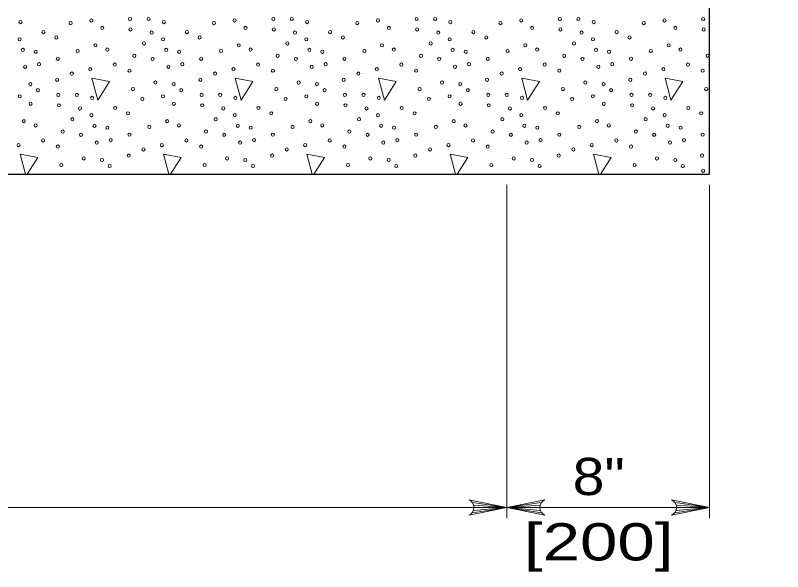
# Model space of a CAD drawing. Extents: x 1352.5 to 1386.5, y 735.9 to 779.9.
# Drawn here: x 1364.306 to 1367.523, y 768.997 to 771.328 of the extents above; entities that cross this region are included whole.
import ezdxf
from ezdxf.enums import TextEntityAlignment as Align

# ---------------------------------------------------------------- set-up
doc = ezdxf.new("R2010")
doc.units = 0
doc.header["$LTSCALE"] = 0.062
doc.layers.add('1', color=7, linetype='Continuous', lineweight=13)

msp = doc.modelspace()

# ---------------------------------------------------------------- linework, layer by layer
at = {"layer": '1'}
for p, q in [((1364.32675, 770.747), (1364.34892, 770.6625)), ((1364.4005, 770.73258), (1364.32675, 770.747)), ((1364.35592, 770.6625), (1364.4005, 770.73258)), ((1364.9275, 770.747), (1364.94967, 770.6625)), ((1365.00125, 770.73258), (1364.9275, 770.747)), ((1364.95667, 770.6625), (1365.00125, 770.73258)), ((1365.52825, 770.747), (1365.5505, 770.6625)), ((1365.602, 770.73258), (1365.52825, 770.747)), ((1365.55733, 770.6625), (1365.602, 770.73258)), ((1366.129, 770.747), (1366.15117, 770.66242)), ((1366.20275, 770.73258), (1366.129, 770.747)), ((1366.15808, 770.66242), (1366.20275, 770.73258)), ((1366.72975, 770.747), (1366.752, 770.66242)), ((1366.8035, 770.73258), (1366.72975, 770.747)), ((1366.75883, 770.66242), (1366.8035, 770.73258)), ((1366.36658, 770.61742), (1366.36658, 769.22067)), ((1367.21625, 770.61742), (1367.21625, 769.22067)), ((1366.22242, 769.28583), (1366.36658, 769.26567)), ((1366.51083, 769.28583), (1366.36658, 769.26567)), ((1367.072, 769.28583), (1367.21625, 769.26567)), ((1366.22067, 769.24333), (1366.36658, 769.26567)), ((1366.22625, 769.25275), (1366.36658, 769.26567)), ((1366.22725, 769.27583), (1366.36658, 769.26567)), ((1366.22875, 769.26567), (1366.36658, 769.26567)), ((1366.50592, 769.27583), (1366.36658, 769.26567)), ((1366.5045, 769.26567), (1366.36658, 769.26567)), ((1366.507, 769.25275), (1366.36658, 769.26567)), ((1366.5125, 769.24333), (1366.36658, 769.26567)), ((1367.07033, 769.24333), (1367.21625, 769.26567)), ((1367.07583, 769.25275), (1367.21625, 769.26567)), ((1367.07692, 769.27583), (1367.21625, 769.26567)), ((1367.07833, 769.26567), (1367.21625, 769.26567))]:
    msp.add_line(p, q, dxfattribs=at)
at = {"layer": '1', "lineweight": 25}
msp.add_lwpolyline([(1358.38042, 774.73258), (1359.56983, 774.73258), (1359.56983, 770.66242), (1367.21625, 770.66242), (1367.21625, 774.73258), (1368.40567, 774.73258), (1369.78625, 774.73258)], dxfattribs=at)
at = {"layer": '1'}
for points in [[(1364.62717, 771.065), (1364.65142, 770.97283), (1364.70083, 771.05067)], [(1365.22783, 771.065), (1365.25217, 770.97283), (1365.30167, 771.05067)], [(1365.82858, 771.065), (1365.85292, 770.97283), (1365.90242, 771.05067)], [(1366.42942, 771.065), (1366.45367, 770.97283), (1366.50308, 771.05067)], [(1367.03017, 771.065), (1367.05442, 770.97283), (1367.10392, 771.05067)]]:
    msp.add_lwpolyline(points, close=True, dxfattribs=at)
for points in [[(1366.20733, 769.23383), (1366.36658, 769.26567), (1366.20733, 769.2975)], [(1366.52592, 769.23383), (1366.36658, 769.26567), (1366.52592, 769.2975)], [(1367.05692, 769.23383), (1367.21625, 769.26567), (1367.05692, 769.2975)], [(1359.56983, 769.26567), (1360.1195, 769.26567), (1360.41942, 769.26567), (1363.67817, 769.26567), (1366.36658, 769.26567), (1366.95142, 769.26567), (1367.21625, 769.26567)]]:
    msp.add_lwpolyline(points, dxfattribs=at)
for centre, start, end in [((1366.19445, 769.2657), 292.08605, 67.91218), ((1366.53878, 769.2657), 112.08782, 247.91395), ((1367.04405, 769.2657), 292.08605, 67.91218)]:
    msp.add_arc(centre, 0.03438, start, end, dxfattribs=at)
for centre in [(1364.62447, 771.30712), (1364.78642, 771.3131), (1364.86432, 771.3131), (1365.22523, 771.30712), (1365.38718, 771.3131), (1365.46508, 771.3131), (1365.82599, 771.30712), (1365.98794, 771.3131), (1366.06584, 771.3131), (1366.42674, 771.30712), (1366.5887, 771.3131), (1366.6666, 771.3131), (1367.0275, 771.30712), (1367.18946, 771.3131), (1364.32759, 771.30023), (1364.53771, 771.29593), (1364.67018, 771.2759), (1364.92835, 771.30023), (1365.13847, 771.29593), (1365.27094, 771.2759), (1365.52911, 771.30023), (1365.73923, 771.29593), (1365.87169, 771.2759), (1366.12987, 771.30023), (1366.33998, 771.29593), (1366.47245, 771.2759), (1366.73063, 771.30023), (1366.94074, 771.29593), (1367.07321, 771.2759), (1364.42412, 771.25814), (1364.78883, 771.26932), (1364.87729, 771.25645), (1365.02487, 771.25814), (1365.38958, 771.26932), (1365.47805, 771.25645), (1365.62563, 771.25814), (1365.99034, 771.26932), (1366.0788, 771.25645), (1366.22639, 771.25814), (1366.5911, 771.26932), (1366.67956, 771.25645), (1366.82715, 771.25814), (1367.19186, 771.26932), (1364.32434, 771.22809), (1364.47763, 771.23583), (1364.8456, 771.21092), (1364.9251, 771.22809), (1365.07839, 771.23583), (1365.44636, 771.21092), (1365.52586, 771.22809), (1365.67915, 771.23583), (1366.04711, 771.21092), (1366.12661, 771.22809), (1366.27991, 771.23583), (1366.64787, 771.21092), (1366.72737, 771.22809), (1366.88067, 771.23583), (1364.33736, 771.18346), (1364.39168, 771.17567), (1364.56715, 771.1789), (1364.64179, 771.20291), (1364.69125, 771.18489), (1364.93812, 771.18346), (1364.99243, 771.17567), (1365.16791, 771.1789), (1365.24255, 771.20291), (1365.29201, 771.18489), (1365.53887, 771.18346), (1365.59319, 771.17567), (1365.76866, 771.1789), (1365.84331, 771.20291), (1365.89277, 771.18489), (1366.13963, 771.18346), (1366.19395, 771.17567), (1366.36942, 771.1789), (1366.44407, 771.20291), (1366.49353, 771.18489), (1366.74039, 771.18346), (1366.79471, 771.17567), (1366.97018, 771.1789), (1367.04482, 771.20291), (1367.09429, 771.18489), (1364.48414, 771.14646), (1364.8048, 771.15913), (1364.88129, 771.14567), (1365.0849, 771.14646), (1365.40555, 771.15913), (1365.48205, 771.14567), (1365.68566, 771.14646), (1366.00631, 771.15913), (1366.08281, 771.14567), (1366.28642, 771.14646), (1366.60707, 771.15913), (1366.68357, 771.14567), (1366.88717, 771.14646), (1367.20783, 771.15913), (1364.34702, 771.11302), (1364.40544, 771.12336), (1364.72284, 771.12219), (1364.94778, 771.11302), (1365.0062, 771.12336), (1365.3236, 771.12219), (1365.54854, 771.11302), (1365.60696, 771.12336), (1365.92436, 771.12219), (1366.14929, 771.11302), (1366.20772, 771.12336), (1366.52512, 771.12219), (1366.75005, 771.11302), (1366.80847, 771.12336), (1367.12588, 771.12219), (1364.54277, 771.0844), (1364.61986, 771.10242), (1364.78452, 771.09643), (1365.14352, 771.0844), (1365.22062, 771.10242), (1365.38528, 771.09643), (1365.74428, 771.0844), (1365.82138, 771.10242), (1365.98604, 771.09643), (1366.34504, 771.0844), (1366.42214, 771.10242), (1366.5868, 771.09643), (1366.9458, 771.0844), (1367.0229, 771.10242), (1367.18755, 771.09643), (1364.48119, 771.05864), (1364.89321, 771.04666), (1365.08195, 771.05864), (1365.49397, 771.04666), (1365.6827, 771.05864), (1366.09472, 771.04666), (1366.28346, 771.05864), (1366.69548, 771.04666), (1366.88422, 771.05864), (1364.369, 771.04004), (1364.40089, 771.01486), (1364.79914, 771.01915), (1364.96976, 771.04004), (1365.00165, 771.01486), (1365.3999, 771.01915), (1365.57051, 771.04004), (1365.6024, 771.01486), (1366.00066, 771.01915), (1366.17127, 771.04004), (1366.20316, 771.01486), (1366.60141, 771.01915), (1366.77203, 771.04004), (1366.80392, 771.01486), (1367.20217, 771.01915), (1364.32409, 770.9891), (1364.48604, 770.99509), (1364.56394, 770.99509), (1364.62797, 770.98221), (1364.92485, 770.9891), (1365.0868, 770.99509), (1365.1647, 770.99509), (1365.22873, 770.98221), (1365.52561, 770.9891), (1365.68756, 770.99509), (1365.76546, 770.99509), (1365.82949, 770.98221), (1366.12636, 770.9891), (1366.28832, 770.99509), (1366.36622, 770.99509), (1366.43025, 770.98221), (1366.72712, 770.9891), (1366.88908, 770.99509), (1366.96697, 770.99509), (1367.03101, 770.98221), (1364.3698, 770.95788), (1364.48845, 770.95131), (1364.83809, 770.97792), (1364.97056, 770.95788), (1365.08921, 770.95131), (1365.43885, 770.97792), (1365.57131, 770.95788), (1365.68996, 770.95131), (1366.0396, 770.97792), (1366.17207, 770.95788), (1366.29072, 770.95131), (1366.64036, 770.97792), (1366.77283, 770.95788), (1366.89148, 770.95131), (1364.57691, 770.93843), (1364.7245, 770.94013), (1364.77801, 770.91781), (1365.17767, 770.93843), (1365.32525, 770.94013), (1365.37877, 770.91781), (1365.77843, 770.93843), (1365.92601, 770.94013), (1365.97953, 770.91781), (1366.37918, 770.93843), (1366.52677, 770.94013), (1366.58029, 770.91781), (1366.97994, 770.93843), (1367.12753, 770.94013), (1367.18104, 770.91781), (1364.54522, 770.8929), (1364.62472, 770.91007), (1365.14598, 770.8929), (1365.22548, 770.91007), (1365.74674, 770.8929), (1365.82624, 770.91007), (1366.34749, 770.8929), (1366.42699, 770.91007), (1366.94825, 770.8929), (1367.02775, 770.91007), (1364.34141, 770.8849), (1364.39087, 770.86688), (1364.63774, 770.86545), (1364.69205, 770.85765), (1364.86753, 770.86089), (1364.94217, 770.8849), (1364.99163, 770.86688), (1365.23849, 770.86545), (1365.29281, 770.85765), (1365.46828, 770.86089), (1365.54293, 770.8849), (1365.59239, 770.86688), (1365.83925, 770.86545), (1365.89357, 770.85765), (1366.06904, 770.86089), (1366.14369, 770.8849), (1366.19315, 770.86688), (1366.44001, 770.86545), (1366.49433, 770.85765), (1366.6698, 770.86089), (1366.74444, 770.8849), (1366.79391, 770.86688), (1367.04077, 770.86545), (1367.09509, 770.85765), (1364.50442, 770.84112), (1364.58091, 770.82766), (1364.78452, 770.82845), (1365.10518, 770.84112), (1365.18167, 770.82766), (1365.38528, 770.82845), (1365.70593, 770.84112), (1365.78243, 770.82766), (1365.98604, 770.82845), (1366.30669, 770.84112), (1366.38319, 770.82766), (1366.5868, 770.82845), (1366.90745, 770.84112), (1366.98395, 770.82766), (1367.18755, 770.82845), (1364.42246, 770.80417), (1364.6474, 770.79501), (1364.70582, 770.80534), (1365.02322, 770.80417), (1365.24816, 770.79501), (1365.30658, 770.80534), (1365.62398, 770.80417), (1365.84891, 770.79501), (1365.90734, 770.80534), (1366.22474, 770.80417), (1366.44967, 770.79501), (1366.5081, 770.80534), (1366.8255, 770.80417), (1367.05043, 770.79501), (1367.10885, 770.80534), (1364.31948, 770.7844), (1364.48414, 770.77842), (1364.84315, 770.76638), (1364.92024, 770.7844), (1365.0849, 770.77842), (1365.4439, 770.76638), (1365.521, 770.7844), (1365.68566, 770.77842), (1366.04466, 770.76638), (1366.12176, 770.7844), (1366.28642, 770.77842), (1366.64542, 770.76638), (1366.72252, 770.7844), (1366.88717, 770.77842), (1364.59283, 770.72865), (1364.78157, 770.74062), (1365.19359, 770.72865), (1365.38233, 770.74062), (1365.79435, 770.72865), (1365.98308, 770.74062), (1366.3951, 770.72865), (1366.58384, 770.74062), (1366.99586, 770.72865), (1367.1846, 770.74062), (1364.49876, 770.70114), (1364.66938, 770.72202), (1364.70127, 770.69684), (1365.09952, 770.70114), (1365.27013, 770.72202), (1365.30202, 770.69684), (1365.70028, 770.70114), (1365.87089, 770.72202), (1365.90278, 770.69684), (1366.30103, 770.70114), (1366.47165, 770.72202), (1366.50354, 770.69684), (1366.90179, 770.70114), (1367.07241, 770.72202), (1367.1043, 770.69684), (1367.18946, 770.67707)]:
    msp.add_ellipse(centre, major_axis=(0, 0.0068), ratio=0.944544, dxfattribs=at)

# ---------------------------------------------------------------- texts
for s, width, p in [('8"', 1.15, (1366.75158, 769.31758)), ('[200]', 1.35, (1366.75158, 769.04358))]:
    msp.add_text(s, height=0.156, dxfattribs=dict(at, width=width)).set_placement(p, align=Align.CENTER)

doc.saveas('drawing.dxf')
